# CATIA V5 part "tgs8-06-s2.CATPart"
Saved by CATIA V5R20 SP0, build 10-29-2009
Part number: TGS8-06-S2
Revision: 1
Definition: design
Nomenclature: TGS8-06-S2
Source: made
Description: NOT SPECIFIED
Bounding box of the stored display mesh (mm): x -3 to 3, y -8 to 0, z -22 to 0.6
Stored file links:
  C:\Users\Raffaele\Desktop\3D X SITO CF\I-MOLD\TGS-S2\tgs8-s2.step\tgs8-06-s2.CATPart
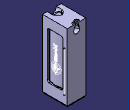
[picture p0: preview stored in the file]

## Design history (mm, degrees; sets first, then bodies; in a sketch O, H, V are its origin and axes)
Set1
  DatumCurve1 "COMPOSITE_CURVE #4072"
  DatumCurve2 "COMPOSITE_CURVE #4118"
  DatumCurve3 "COMPOSITE_CURVE #4351"
  DatumCurve4 "COMPOSITE_CURVE #4411"
  DatumCurve5 "COMPOSITE_CURVE #4468"
  DatumCurve6 "COMPOSITE_CURVE #4629"
  DatumCurve7 "COMPOSITE_CURVE #4656"
  DatumCurve8 "COMPOSITE_CURVE #4683"
  DatumCurve9 "COMPOSITE_CURVE #4766"
  DatumCurve10 "COMPOSITE_CURVE #4817"
  Line1 "LINE #4821": stored without definition
  DatumSurface1 "OPEN_SHELL #4021"
Body1 "MANIFOLD_SOLID_BREP #4022" (main body)
  Solid1: solid without history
